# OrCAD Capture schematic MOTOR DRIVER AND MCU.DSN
size B
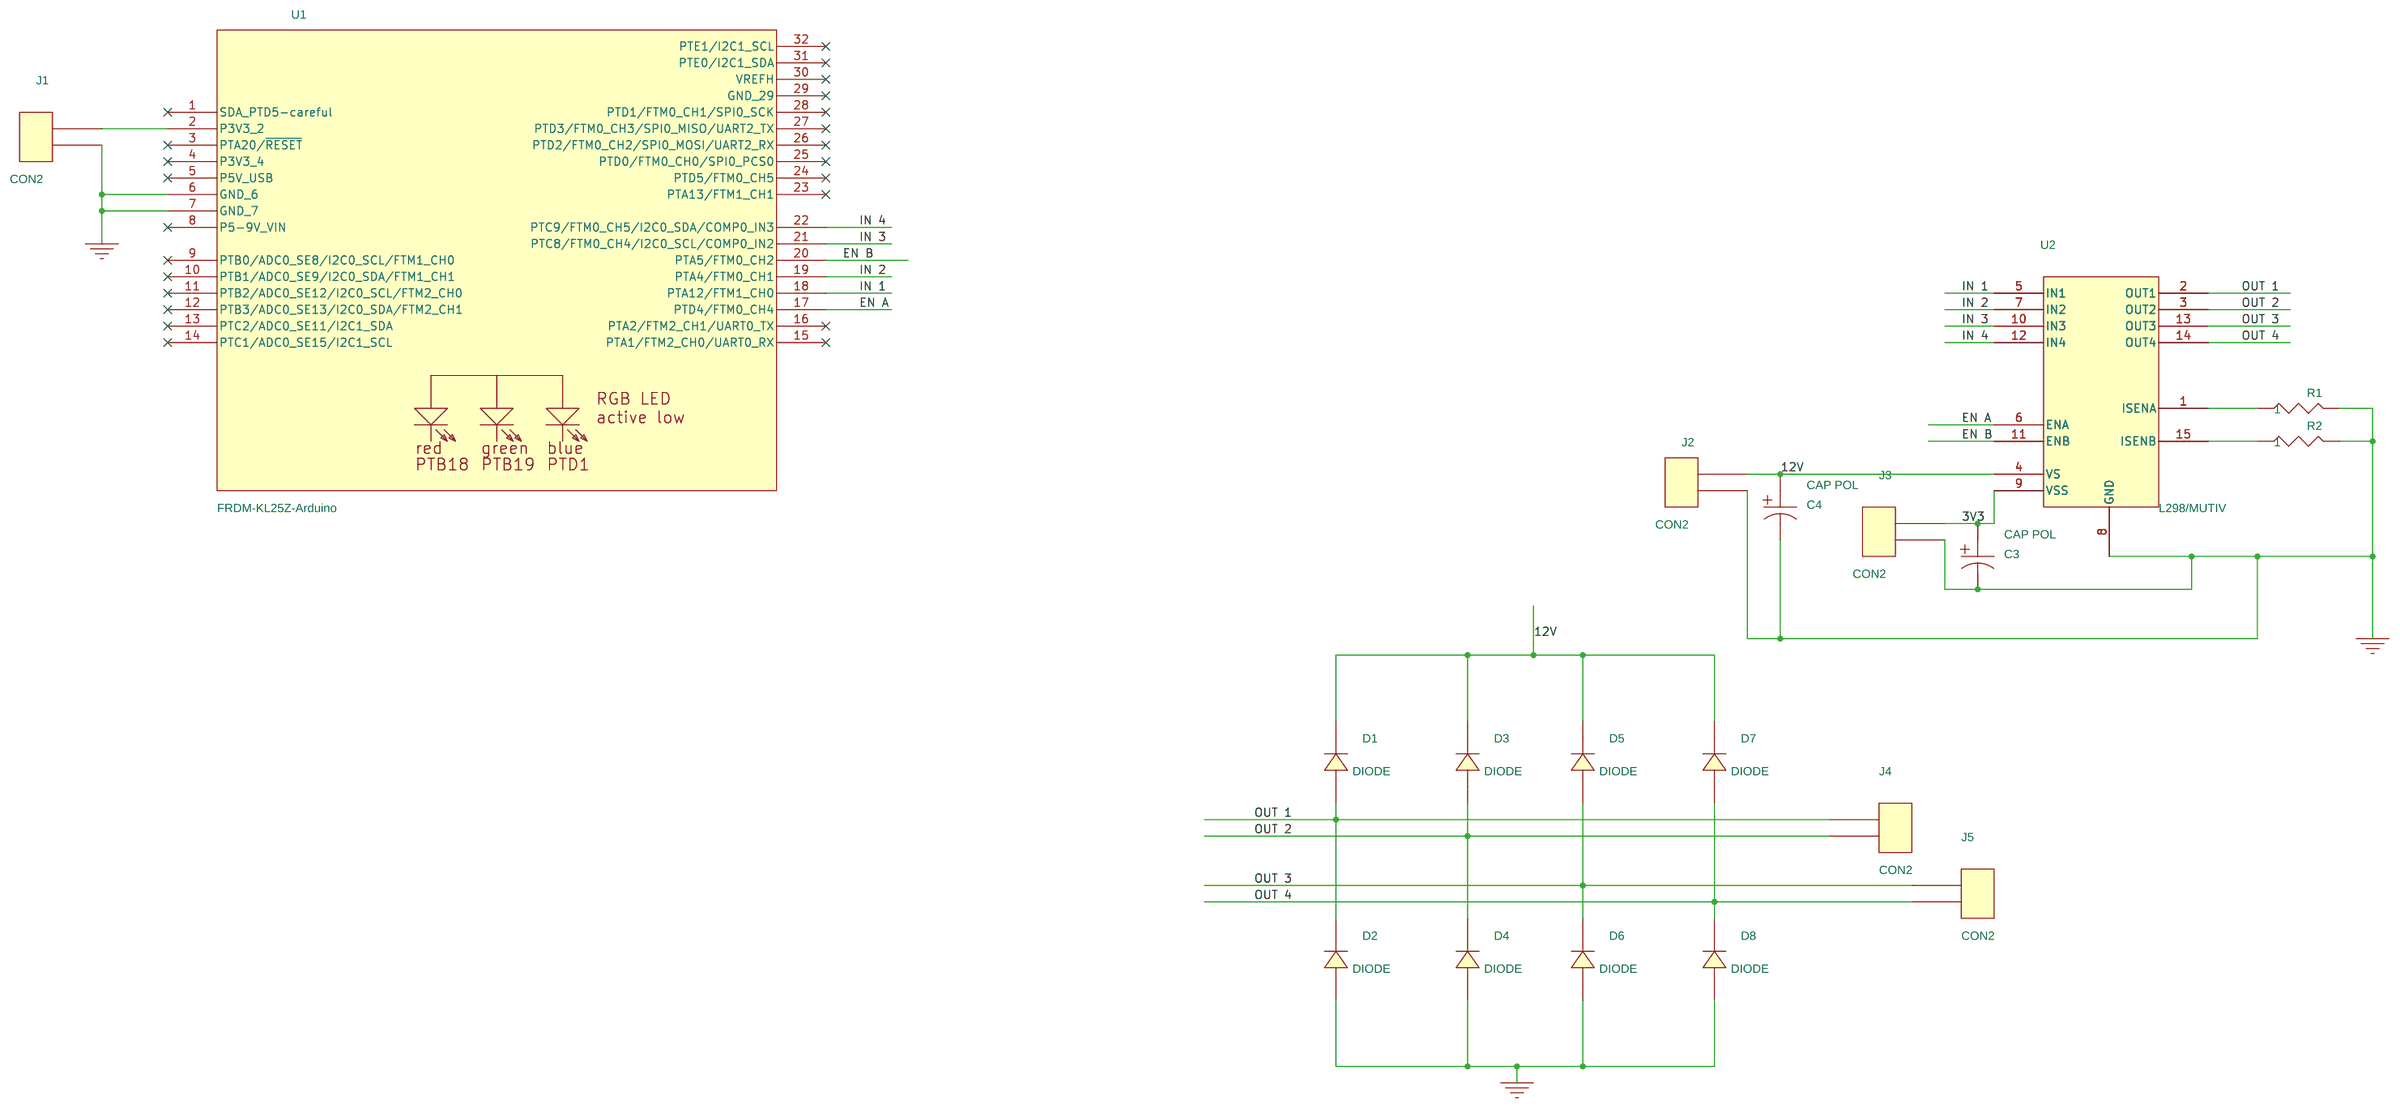
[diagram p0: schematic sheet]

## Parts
C3  CAP POL  [GU-CAPCYL200]
C4  CAP POL  [GU-CAPCYL200]
D1  DIODE  [GU-1N4001]
D2  DIODE  [GU-1N4001]
D3  DIODE  [GU-1N4001]
D4  DIODE  [GU-1N4001]
D5  DIODE  [GU-1N4001]
D6  DIODE  [GU-1N4001]
D7  DIODE  [GU-1N4001]
D8  DIODE  [GU-1N4001]
J1  CON2  [GU-terminal2-200]
J2  CON2  [GU-terminal2-200]
J3  CON2  [GU-terminal2-200]
J4  CON2  [GU-terminal2-200]
J5  CON2  [GU-terminal2-200]
R1  1  [GU-RC400]
R2  1  [GU-RC400]
U1  FRDM-KL25Z-Arduino  [gu-frdm-arduino]
U2  L298/MUTIV  [GU-L298-HSINK2]

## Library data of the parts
C3 C4 = CAP_POL
D1-D8 = DIODE
J1-J5 = CON2
R1 R2 = R
U1 = FRDM-KL25Z-Arduino
U2 = L298_MUTIV_0

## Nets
3V3: C3.1 J3.1 U2.9(VSS)
12V: C4.1 D1.1(K) D3.1(K) D5.1(K) D7.1(K) J2.1 U2.4(VS)
GND: C3.2 C4.2 D2.2(A) D4.2(A) D6.2(A) D8.2(A) J1.2 J2.2 J3.2 R1.2 R2.2 U1.6(GND) U1.7(GND) U2.8(GND)
EN A: U1.17(PTD4/FTM0_CH4) U2.6(ENA)
EN B: U1.20(PTA5/FTM0_CH2) U2.11(ENB)
IN 1: U1.18(PTA12/FTM1_CH0) U2.5(IN1)
IN 2: U1.19(PTA4/FTM0_CH1) U2.7(IN2)
IN 3: U1.21(PTC8/FTM0_CH4/I2C0_SCL/COMP0_IN2) U2.10(IN3)
IN 4: U1.22(PTC9/FTM0_CH5/I2C0_SDA/COMP0_IN3) U2.12(IN4)
OUT 1: D1.2(A) D2.1(K) J4.1 U2.2(OUT1)
OUT 2: D3.2(A) D4.1(K) J4.2 U2.3(OUT2)
OUT 3: D5.2(A) D6.1(K) J5.1 U2.13(OUT3)
OUT 4: D7.2(A) D8.1(K) J5.2 U2.14(OUT4)
N00758: J1.1 U1.2(P3V3)
N01131: R1.1 U2.1(ISENA)
N01135: R2.1 U2.15(ISENB)

Not connected (* = marked no-connect by the designer): U1 1(SDA_PTD5-careful)* 3(PTA20/~{RESET})* 4(P3V3)* 5(P5V_USB)* 8(P5-9V_VIN)* 9(PTB0/ADC0_SE8/I2C0_SCL/FTM1_CH0)* 10(PTB1/ADC0_SE9/I2C0_SDA/FTM1_CH1)* 11(PTB2/ADC0_SE12/I2C0_SCL/FTM2_CH0)* 12(PTB3/ADC0_SE13/I2C0_SDA/FTM2_CH1)* 13(PTC2/ADC0_SE11/I2C1_SDA)* 14(PTC1/ADC0_SE15/I2C1_SCL)* 15(PTA1/FTM2_CH0/UART0_RX)* 16(PTA2/FTM2_CH1/UART0_TX)* 23(PTA13/FTM1_CH1)* 24(PTD5/FTM0_CH5)* 25(PTD0/FTM0_CH0/SPI0_PCS0)* 26(PTD2/FTM0_CH2/SPI0_MOSI/UART2_RX)* 27(PTD3/FTM0_CH3/SPI0_MISO/UART2_TX)* 28(PTD1/FTM0_CH1/SPI0_SCK)* 29(GND)* 30(VREFH)* 31(PTE0/I2C1_SDA)* 32(PTE1/I2C1_SCL)*
